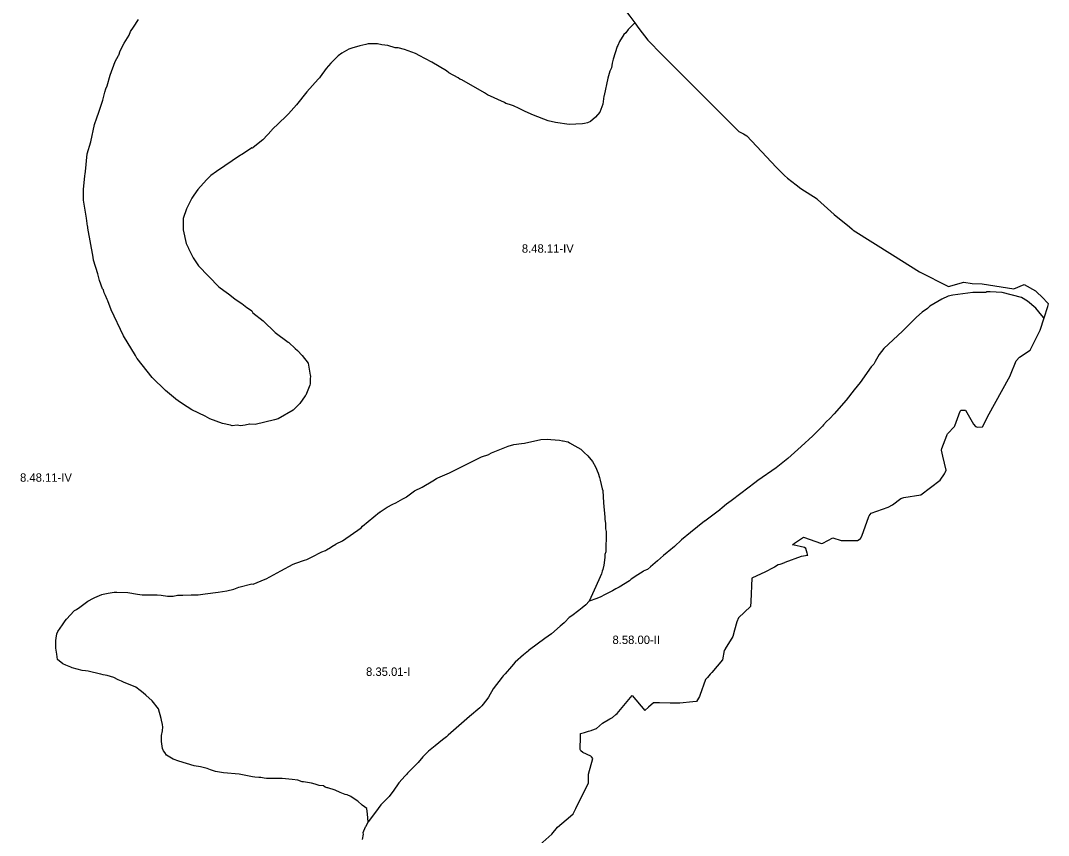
# Model space of a CAD drawing. Extents: x -444937 to -440470, y -1149084 to -1129741.
# Drawn here: x -441693 to -440470, y -1132010 to -1131040 of the extents above; entities that cross this region are included whole.
import ezdxf

# ---------------------------------------------------------------- set-up
doc = ezdxf.new("R2010")
doc.units = 0
doc.layers.add('Vrstva 28', color=7, linetype='Continuous')

msp = doc.modelspace()

# ---------------------------------------------------------------- linework, layer by layer
at = {"layer": 'Vrstva 28'}
for points in [[(-441127.2, -1130789.51), (-441083.55, -1130863.55), (-441069.43, -1130886.07), (-441056, -1130907.27), (-441045.35, -1130923.53), (-441032.99, -1130942.46), (-441030.18, -1130946.6), (-440989.66, -1131006.42), (-440983.75, -1131015.14), (-440968.54, -1131035.29), (-440962.58, -1131043.2)], [(-441430.08, -1131376.9), (-441424.12, -1131381.79), (-441420.72, -1131383.7), (-441418.17, -1131385.83), (-441416.89, -1131387.95), (-441404.56, -1131397.52), (-441390.11, -1131411.34), (-441374.8, -1131422.82), (-441374.21, -1131423.36), (-441366.43, -1131430.38), (-441363.75, -1131432.81), (-441358.22, -1131438.76), (-441351.2, -1131448.12), (-441348.55, -1131462.42), (-441348.44, -1131463), (-441348.58, -1131466.82), (-441348.65, -1131468.95), (-441348.8, -1131472.49), (-441348.86, -1131474.05), (-441353.97, -1131485.96), (-441354.61, -1131486.9), (-441360.77, -1131495.95), (-441363.73, -1131498.91), (-441368.85, -1131504.03), (-441386.71, -1131514.24), (-441391.19, -1131515.35), (-441413.92, -1131521.04), (-441420.54, -1131520.62), (-441420.72, -1131520.61), (-441425.83, -1131521.53), (-441431.35, -1131522.53), (-441435.6, -1131521.89), (-441441.56, -1131522.53), (-441443.26, -1131521.68), (-441453.04, -1131519.76), (-441467.92, -1131514.24), (-441473.66, -1131510.83), (-441489.6, -1131503.39), (-441500.66, -1131496.17), (-441505.6, -1131492.69), (-441508.52, -1131490.64), (-441508.86, -1131490.36), (-441520.64, -1131480.65), (-441536.59, -1131464.91), (-441554.33, -1131442.37), (-441554.66, -1131441.95), (-441556.57, -1131438.78), (-441570.6, -1131415.59), (-441585.48, -1131384.34), (-441589.31, -1131373.71), (-441590.11, -1131372.04), (-441592.29, -1131367.47), (-441593.77, -1131364.36), (-441594.63, -1131360.74), (-441595.69, -1131359.47), (-441599.09, -1131349.47), (-441601.39, -1131341.84), (-441606.32, -1131325.45), (-441606.95, -1131321.86), (-441613.02, -1131287.38), (-441613.3, -1131285.63), (-441613.43, -1131284.81), (-441614.89, -1131275.49), (-441618.22, -1131254.23), (-441618.22, -1131248.85), (-441618.22, -1131241.48), (-441616.57, -1131224.93), (-441616.34, -1131222.69), (-441616.08, -1131220.09), (-441613.97, -1131198.96), (-441609.72, -1131184.5), (-441605.04, -1131164.09), (-441602.43, -1131156.2), (-441600.18, -1131149.39), (-441595.48, -1131135.18), (-441592.83, -1131125.77), (-441591.65, -1131121.57), (-441589.95, -1131118.17), (-441586.76, -1131105.41), (-441580.59, -1131089.26), (-441576.61, -1131082.09), (-441576.34, -1131081.6), (-441574.64, -1131076.5), (-441569.96, -1131067.15), (-441564.01, -1131057.79), (-441562.31, -1131053.54), (-441558.67, -1131048.1), (-441552.77, -1131039.3)], [(-440962.58, -1131043.2), (-440969.34, -1131049.89), (-440970.44, -1131050.99), (-440973.21, -1131055.03), (-440975.34, -1131056.94), (-440980.65, -1131065.23), (-440982.78, -1131069.98), (-440983.41, -1131071.4), (-440988.3, -1131086.28), (-440989.22, -1131091.16), (-440990.22, -1131096.49), (-440992.13, -1131100.74), (-440994.47, -1131109.03), (-440998.96, -1131129.67), (-440999.15, -1131130.5), (-441000.42, -1131139.85), (-441004.25, -1131149.21), (-441009.35, -1131155.37), (-441015.09, -1131160.48), (-441018.92, -1131162.18), (-441022.39, -1131162.92), (-441024.87, -1131163.45), (-441040.6, -1131163.88), (-441056.76, -1131161.75), (-441065.69, -1131159.84), (-441083.12, -1131153.04), (-441089.22, -1131150.2), (-441093.64, -1131148.15), (-441100.16, -1131145.13), (-441106.93, -1131141.98), (-441111.59, -1131140.43), (-441115.86, -1131139), (-441117.56, -1131137.73), (-441137.55, -1131128.8), (-441141.39, -1131126.56), (-441168.16, -1131110.94), (-441170.71, -1131110.09), (-441172.41, -1131108.6), (-441183.89, -1131102.65), (-441186.65, -1131100.31), (-441203.87, -1131089.89), (-441219.06, -1131081.97), (-441222.64, -1131080.11), (-441223.43, -1131079.69), (-441236.62, -1131074.8), (-441244.06, -1131072.89), (-441247.67, -1131072.67), (-441250, -1131071.98), (-441254.04, -1131070.76), (-441256.17, -1131070.12), (-441263.4, -1131069.49), (-441268.5, -1131068.21), (-441279.56, -1131068.21), (-441282.24, -1131068.77), (-441289.76, -1131070.34), (-441299.02, -1131073.42), (-441302.52, -1131074.59), (-441311.02, -1131079.26), (-441315.27, -1131082.45), (-441324.2, -1131090.96), (-441329.73, -1131097.34), (-441336.71, -1131107.33), (-441337.6, -1131108.6), (-441339.09, -1131110.26), (-441352.69, -1131125.4), (-441364.81, -1131140.7), (-441374.54, -1131151.26), (-441377.35, -1131154.31), (-441394.21, -1131170.55), (-441394.79, -1131171.11), (-441404.76, -1131181.92), (-441404.99, -1131182.16), (-441416.41, -1131191.62), (-441417.32, -1131192.37), (-441417.96, -1131191.94), (-441423.2, -1131195.27), (-441430.12, -1131199.67), (-441431.35, -1131200.45), (-441460.27, -1131219.79), (-441466.64, -1131224.68), (-441472.17, -1131229.99), (-441482.16, -1131241.26), (-441486.97, -1131247.99), (-441489.6, -1131251.68), (-441495.77, -1131264.22), (-441499.59, -1131275.7), (-441499.75, -1131285.7), (-441499.81, -1131289.52), (-441496.19, -1131305.68), (-441493.51, -1131311.05), (-441493.32, -1131311.42), (-441491.35, -1131315.37), (-441487.69, -1131322.69), (-441481.52, -1131332.04), (-441457.5, -1131357.34), (-441446.9, -1131364.54), (-441446.23, -1131364.99), (-441437.73, -1131372.01), (-441430.08, -1131376.9)], [(-440962.58, -1131043.2), (-440957.6, -1131049.79), (-440947.06, -1131063.76), (-440929.78, -1131081.2), (-440919.44, -1131091.64), (-440909.18, -1131102), (-440905.35, -1131105.86), (-440880.72, -1131130.44), (-440838.53, -1131172.54), (-440835.42, -1131174.15), (-440833.3, -1131175.26), (-440829.22, -1131177.38), (-440805.74, -1131202.33), (-440794.14, -1131214.66), (-440784.52, -1131224.88), (-440780.72, -1131227.89), (-440770.54, -1131235.95), (-440764.94, -1131240.39), (-440745.64, -1131252.59), (-440745.05, -1131253.13), (-440725.47, -1131270.94), (-440707.24, -1131285.85), (-440703.88, -1131288.69), (-440702.54, -1131289.81), (-440656, -1131319.05), (-440623.64, -1131339.38), (-440589.39, -1131356.6), (-440570.93, -1131351.66), (-440561.09, -1131353.09), (-440549.41, -1131353.46), (-440511.6, -1131359.37), (-440499.15, -1131354.46), (-440485.64, -1131362.06), (-440476.37, -1131371.1), (-440472.56, -1131375.03), (-440470.44, -1131377.22), (-440470.4, -1131377.26)], [(-440475.66, -1131394.12), (-440475.8, -1131393.95), (-440478.14, -1131391.12), (-440485.3, -1131382.43), (-440495.51, -1131374.14), (-440502.31, -1131369.67), (-440525.27, -1131363.93), (-440539.73, -1131363.08), (-440544.19, -1131363.08), (-440544.83, -1131363.72), (-440560.35, -1131363.72), (-440583.95, -1131366.91), (-440589.69, -1131368.39), (-440597.34, -1131371.8), (-440611.37, -1131380.3), (-440614.38, -1131382.88), (-440620.73, -1131387.32), (-440627.32, -1131393.27), (-440643.9, -1131409.85), (-440655.03, -1131420.24), (-440666.22, -1131430.68), (-440671.75, -1131437.49), (-440676.48, -1131446.17), (-440678.13, -1131449.18), (-440681.1, -1131452.37), (-440694.5, -1131471.08), (-440701.32, -1131479.65), (-440711.08, -1131491.91), (-440725.11, -1131508.07), (-440730.57, -1131513.71), (-440731.05, -1131514.21), (-440734.26, -1131517.53), (-440738.08, -1131521.47), (-440739.33, -1131522.76), (-440748.64, -1131532.38), (-440750.09, -1131533.89), (-440750.62, -1131534.43), (-440764.6, -1131547.11), (-440780.39, -1131561.43), (-440794.42, -1131572.49), (-440816.1, -1131587.58), (-440819.76, -1131590.33), (-440836.51, -1131602.89), (-440847.81, -1131611.58), (-440853.24, -1131615.75), (-440858.62, -1131619.89), (-440861.2, -1131622.48), (-440861.38, -1131622.66), (-440861.78, -1131622.95), (-440872.71, -1131631.06), (-440879.25, -1131635.9), (-440879.45, -1131636.05), (-440896.33, -1131649.55), (-440907.09, -1131658.16), (-440915.38, -1131666.03), (-440922, -1131671.64), (-440923.92, -1131673.27), (-440928.23, -1131676.92), (-440935.48, -1131683.07), (-440943.77, -1131690.09), (-440943.99, -1131690.28), (-440947.48, -1131693.24), (-440951.53, -1131695.09), (-440952.59, -1131695.58), (-440958.86, -1131699.7), (-440966.83, -1131704.93), (-440968.74, -1131706.85), (-440981.19, -1131714.24), (-440984.93, -1131716.45), (-440989.15, -1131718.96), (-440997.58, -1131723.18), (-441003.61, -1131726.19), (-441008.99, -1131728.25), (-441015.47, -1131730.73), (-441016.58, -1131731.15)], [(-440475.66, -1131394.12), (-440471.27, -1131380.51), (-440470.4, -1131377.26)], [(-440534.6, -1131496.63), (-440516.13, -1131463), (-440515.7, -1131461.94), (-440508.9, -1131445.14), (-440504.86, -1131440.89), (-440492.11, -1131432.39), (-440484.55, -1131417.27), (-440480.99, -1131410.15), (-440480.2, -1131408.58), (-440475.66, -1131394.12)], [(-440756.49, -1131676.88), (-440757.27, -1131675.01), (-440756.95, -1131674.81), (-440757.25, -1131673.86), (-440758.91, -1131668.58), (-440760.4, -1131667.09), (-440774.4, -1131664.11), (-440774.96, -1131663.99), (-440772.31, -1131662.2), (-440761.64, -1131655.01), (-440740.42, -1131662.41), (-440738.72, -1131662.2), (-440726.81, -1131655.61), (-440717.03, -1131658.8), (-440697.05, -1131658.8), (-440696.69, -1131658.54), (-440693.86, -1131656.46), (-440692.37, -1131653.91), (-440684.02, -1131630.49), (-440683.65, -1131629.46), (-440681.32, -1131626.49), (-440660.91, -1131619.26), (-440655.8, -1131616.28), (-440646.02, -1131609.05), (-440642.62, -1131607.56), (-440622.21, -1131604.38), (-440599.04, -1131587.16), (-440594.15, -1131579.5), (-440593.45, -1131577.95), (-440592.24, -1131575.25), (-440595.94, -1131558.66), (-440597.55, -1131551.44), (-440597.34, -1131549.53), (-440591.35, -1131534.18), (-440590.76, -1131532.66), (-440590.54, -1131532.09), (-440582.23, -1131523.19), (-440581.61, -1131522.53), (-440576.95, -1131509.36), (-440575.44, -1131505.09), (-440574.17, -1131504.03), (-440569.03, -1131503.7), (-440559.5, -1131520.61), (-440557.16, -1131523.38), (-440554.61, -1131524.01), (-440548.66, -1131523.8), (-440541, -1131508.28), (-440534.6, -1131496.63)], [(-441578.68, -1131720.54), (-441565.71, -1131720.88), (-441553.91, -1131722.8), (-441548.7, -1131723.64), (-441531.7, -1131723.44), (-441530.85, -1131723.43), (-441525.92, -1131724.02), (-441518.52, -1131724.92), (-441516.02, -1131724.92), (-441511.71, -1131724.92), (-441506.61, -1131723.85), (-441501.6, -1131723.81), (-441500.18, -1131723.8), (-441490.33, -1131723.71), (-441481.95, -1131723.64), (-441473.63, -1131722.45), (-441458.24, -1131720.23), (-441452.97, -1131719.48), (-441447.93, -1131718.75), (-441439.43, -1131716.84), (-441433.48, -1131714.29), (-441418.17, -1131710.46), (-441416.47, -1131710.67), (-441402.01, -1131704.93), (-441401.15, -1131704.47), (-441383.53, -1131694.98), (-441368.85, -1131687.07), (-441365.61, -1131685.97), (-441355.41, -1131682.48), (-441352.69, -1131681.55), (-441346.95, -1131678.54), (-441334.83, -1131672.19), (-441330.58, -1131670.71), (-441329.24, -1131669.9), (-441324.52, -1131667.07), (-441323.03, -1131666.18), (-441318.22, -1131663.29), (-441317.83, -1131663.05), (-441310.17, -1131659.44), (-441287.85, -1131643.71), (-441286.36, -1131641.79), (-441265.98, -1131625.37), (-441265.53, -1131625), (-441265.44, -1131624.94), (-441256.91, -1131619.23), (-441250.22, -1131615.83), (-441246.82, -1131613.94), (-441238.46, -1131609.49), (-441234.27, -1131607.25), (-441234.06, -1131607.14), (-441224.71, -1131599.91), (-441215.36, -1131595.45), (-441202.91, -1131587.95), (-441198.5, -1131585.3), (-441196.65, -1131584.18), (-441183.04, -1131578.23), (-441167.79, -1131570.68), (-441163.89, -1131568.76), (-441162.3, -1131567.97), (-441157.46, -1131565.58), (-441144.77, -1131559.31), (-441136.27, -1131556.54), (-441135.79, -1131556.27), (-441132.87, -1131554.63), (-441113.31, -1131546.76), (-441106.51, -1131544.85), (-441097.24, -1131543.46), (-441093.75, -1131542.94), (-441074.19, -1131538.68), (-441066.54, -1131538.47), (-441062.28, -1131538.78), (-441052.08, -1131539.53), (-441048.43, -1131540.25), (-441047.76, -1131540.38), (-441042.3, -1131541.45), (-441041.84, -1131541.71), (-441040.02, -1131542.76), (-441033.62, -1131546.44), (-441026.78, -1131550.38), (-441022.52, -1131554.32), (-441018.28, -1131558.24), (-441012.96, -1131565.05), (-441009.14, -1131571.42), (-441005.95, -1131578.65), (-441005.93, -1131578.71), (-441004.62, -1131583.87), (-441003.79, -1131587.1), (-441001.19, -1131597.3), (-441000.63, -1131599.49), (-440999.55, -1131614.17), (-440998.28, -1131631.24), (-440998.08, -1131633.93), (-440997.23, -1131638.18), (-440997.24, -1131638.29), (-440997.45, -1131644.98), (-440996.59, -1131648.38), (-440996.64, -1131651.06), (-440997, -1131670.98), (-440997.02, -1131672.19)], [(-440997.02, -1131672.19), (-440998.3, -1131675.6), (-440998.08, -1131679), (-440999.36, -1131688.35), (-441000.68, -1131693.24), (-441001.27, -1131695.39), (-441002.12, -1131698.56), (-441005.3, -1131705.72)], [(-440756.49, -1131676.88), (-440756.6, -1131676.91), (-440764.68, -1131677.88), (-440783.82, -1131685.02), (-440784.53, -1131685.29), (-440790, -1131687.33), (-440791.8, -1131688), (-440796.45, -1131690.48), (-440800.96, -1131692.89), (-440803.93, -1131694.47), (-440806.8, -1131696), (-440823.24, -1131703.74), (-440824.48, -1131731.49), (-440824.75, -1131737.5), (-440839.3, -1131751), (-440841.24, -1131755.61), (-440843.96, -1131765.59), (-440846, -1131773.05), (-440854.81, -1131787.8), (-440855.11, -1131788.3), (-440856, -1131789.8), (-440858.1, -1131801), (-440864.53, -1131808.48), (-440870.9, -1131815.89), (-440872.74, -1131818.03), (-440875.92, -1131821.73), (-440878.19, -1131824.37), (-440884.98, -1131843.33), (-440885.4, -1131844.5), (-440888.9, -1131850.3), (-440893.44, -1131850.84), (-440908.93, -1131852.23), (-440920.25, -1131852.23), (-440933.19, -1131851.81), (-440936.58, -1131851.9), (-440940.4, -1131852), (-440946.34, -1131857.05), (-440950.43, -1131861.26)], [(-441005.3, -1131705.72), (-441010.76, -1131718.03), (-441016.58, -1131731.15)], [(-441279.53, -1131993.57), (-441280.53, -1131984.35), (-441281.26, -1131977.69), (-441286.79, -1131973.87), (-441291.89, -1131968.98), (-441296.36, -1131966.07), (-441300.39, -1131963.45), (-441304.65, -1131961.32), (-441307.2, -1131960.9), (-441313.04, -1131958.5), (-441319.1, -1131956.01), (-441327.78, -1131953.22), (-441328.43, -1131953.01), (-441331.01, -1131952.18), (-441332.71, -1131950.69), (-441337.81, -1131950.27), (-441342.71, -1131948.82), (-441347.16, -1131947.5), (-441356.55, -1131946.06), (-441358.22, -1131945.8), (-441363.32, -1131944.1), (-441369.95, -1131943.35), (-441382.03, -1131941.98), (-441392.82, -1131941.98), (-441393.85, -1131941.98), (-441400.74, -1131941.98), (-441403.48, -1131941.46), (-441407.54, -1131940.7), (-441409.88, -1131940.63), (-441414.34, -1131940.49), (-441417.27, -1131939.89), (-441433.05, -1131936.66), (-441451.76, -1131935.39), (-441461.11, -1131933.69), (-441467.09, -1131931.57), (-441471.32, -1131930.07), (-441478.97, -1131928.16), (-441486.63, -1131927.1), (-441504.78, -1131921.25), (-441511.71, -1131919.02), (-441519.37, -1131914.13), (-441521.71, -1131911.01), (-441523.19, -1131909.03), (-441524.26, -1131906.47), (-441525.53, -1131897.97), (-441525.32, -1131890.95), (-441524.46, -1131885.21), (-441524.45, -1131885.1), (-441523.83, -1131880.96), (-441524.38, -1131877.8), (-441525.32, -1131872.46), (-441525.81, -1131870.69), (-441528.93, -1131859.28), (-441536.59, -1131849.71), (-441544.03, -1131842.7), (-441547.43, -1131840.08), (-441550.92, -1131837.41), (-441555.93, -1131833.55), (-441570.8, -1131827.31), (-441573.03, -1131826.37), (-441577.19, -1131824.63), (-441582.3, -1131821.86), (-441589.95, -1131819.31), (-441595.05, -1131818.67), (-441597.82, -1131817.98), (-441598.1, -1131817.91), (-441612.91, -1131814.21), (-441616.01, -1131813.92), (-441619.71, -1131813.57), (-441631.62, -1131810.17), (-441633.43, -1131809.42), (-441639.16, -1131807.04), (-441642.88, -1131805.49), (-441649.29, -1131800.54), (-441650.12, -1131794.04), (-441651.02, -1131786.92), (-441651.18, -1131785.72), (-441651.18, -1131785.34), (-441651.18, -1131777.85), (-441650.72, -1131774.95), (-441649.9, -1131769.77), (-441648.84, -1131767.22), (-441643.35, -1131759.05), (-441640.12, -1131754.26), (-441638.56, -1131752.54), (-441629.59, -1131742.71), (-441629.07, -1131742.14), (-441628.11, -1131741.74), (-441626.51, -1131741.08), (-441622.64, -1131738.14), (-441613.33, -1131731.08), (-441606.35, -1131727.42), (-441604.83, -1131726.62), (-441602.13, -1131725.47), (-441596.33, -1131723), (-441594.95, -1131722.76), (-441589.08, -1131721.73), (-441581.87, -1131720.45), (-441578.68, -1131720.54)], [(-441016.58, -1131731.15), (-441020.62, -1131735.34), (-441024.98, -1131738.91), (-441028.91, -1131742.14), (-441037.54, -1131748.53), (-441040.39, -1131750.64), (-441045.82, -1131756.07), (-441046.55, -1131756.81), (-441051.29, -1131760.88), (-441061.65, -1131769.77), (-441069.42, -1131775.5), (-441087.6, -1131788.89), (-441088.81, -1131789.78), (-441089.07, -1131789.97), (-441094.77, -1131794.97), (-441104.59, -1131803.58), (-441109.28, -1131808.89), (-441116.85, -1131817.49), (-441118.9, -1131819.82), (-441120.32, -1131821.44), (-441130.95, -1131835.47), (-441136.59, -1131845.13), (-441138.4, -1131848.22), (-441144.35, -1131855.45), (-441147, -1131857.77), (-441159.01, -1131868.31), (-441171.61, -1131879.35), (-441184.39, -1131890.57), (-441185.8, -1131891.81), (-441186.41, -1131892.29), (-441191.3, -1131896.19), (-441199.94, -1131903.09), (-441207.91, -1131909.45), (-441213.87, -1131915.4), (-441214.54, -1131916.22), (-441220.03, -1131922.84), (-441224.05, -1131926.91), (-441232.86, -1131935.84), (-441234.14, -1131937.14), (-441235.76, -1131938.79), (-441242.99, -1131947.29), (-441250, -1131956.98), (-441252.74, -1131960.76), (-441254.69, -1131963.45), (-441264.68, -1131973.44), (-441270.91, -1131981.89), (-441279.53, -1131993.57)], [(-441075.6, -1132020.75), (-441061.15, -1132008.21), (-441054.29, -1132000), (-441038.78, -1131986.7), (-441035.71, -1131984.07), (-441032.62, -1131977.85), (-441024.51, -1131961.54), (-441017.64, -1131947.72), (-441017.55, -1131942.82), (-441017.43, -1131936.66), (-441012.33, -1131918.17), (-441014.02, -1131916.16), (-441014.66, -1131915.4), (-441024.23, -1131911.15), (-441026.57, -1131909.03), (-441027.42, -1131907.32), (-441027.06, -1131892.15), (-441026.97, -1131888.56), (-441022.32, -1131887.13), (-441017.55, -1131885.66), (-441014.33, -1131885.04), (-441013.74, -1131884.48), (-441007.86, -1131882.66), (-441001.06, -1131876.29), (-440992.23, -1131871.21), (-440989.1, -1131869.41), (-440984.91, -1131865.86), (-440983.41, -1131864.59), (-440965.64, -1131843.37), (-440950.43, -1131861.26)], [(-441279.53, -1131993.57), (-441283.01, -1131999.63), (-441283.17, -1132000), (-441286.01, -1132006.72), (-441285.58, -1132008.21), (-441286.67, -1132014.39)]]:
    msp.add_lwpolyline(points, dxfattribs=at)

# ---------------------------------------------------------------- texts
for s, p in [('8.48.11-IV', (-441096.82, -1131316.57)), ('8.48.11-IV', (-441693.76, -1131589.02)), ('8.58.00-II', (-440989.02, -1131782.02)), ('8.35.01-I', (-441282.18, -1131819.93))]:
    msp.add_text(s, height=10, dxfattribs=at).set_placement(p)

doc.saveas('drawing.dxf')
